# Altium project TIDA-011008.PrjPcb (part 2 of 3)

## Sheet TIDA-011008_Control Stage.SchDoc
size 558 x 431 mm; Date: Not shown in title block; ApprovedBy: Not shown in title block; CheckedBy: Not shown in title block; Author: Not shown in title block; CompanyName: Not shown in title block; Engineer: Not shown in title block; Organization: Not shown in title block; Address1: Not shown in title block; Address2: Not shown in title block; Address3: Not shown in title block; Address4: Not shown in title block; DocumentNumber: 1; Revision: Use project parameter SCH_Rev; SheetNumber: 9; SheetTotal: 10; PageSetup: Record=PageOptions¦CenterHorizontal=True¦CenterVertical=True¦PrintScale=1.00¦XCorrection=1.00¦YCorrection=1.00¦PrintKind=0¦BorderSize=5000000¦LeftOffset=0¦BottomOffset=0¦Orientation=2¦PaperLength=1000¦PaperWidth=1000¦Scale=100¦PaperSource=15¦PrintQuality=600¦MediaType=1¦DitherType=10¦PaperKind=Letter¦PrintScaleMode=1
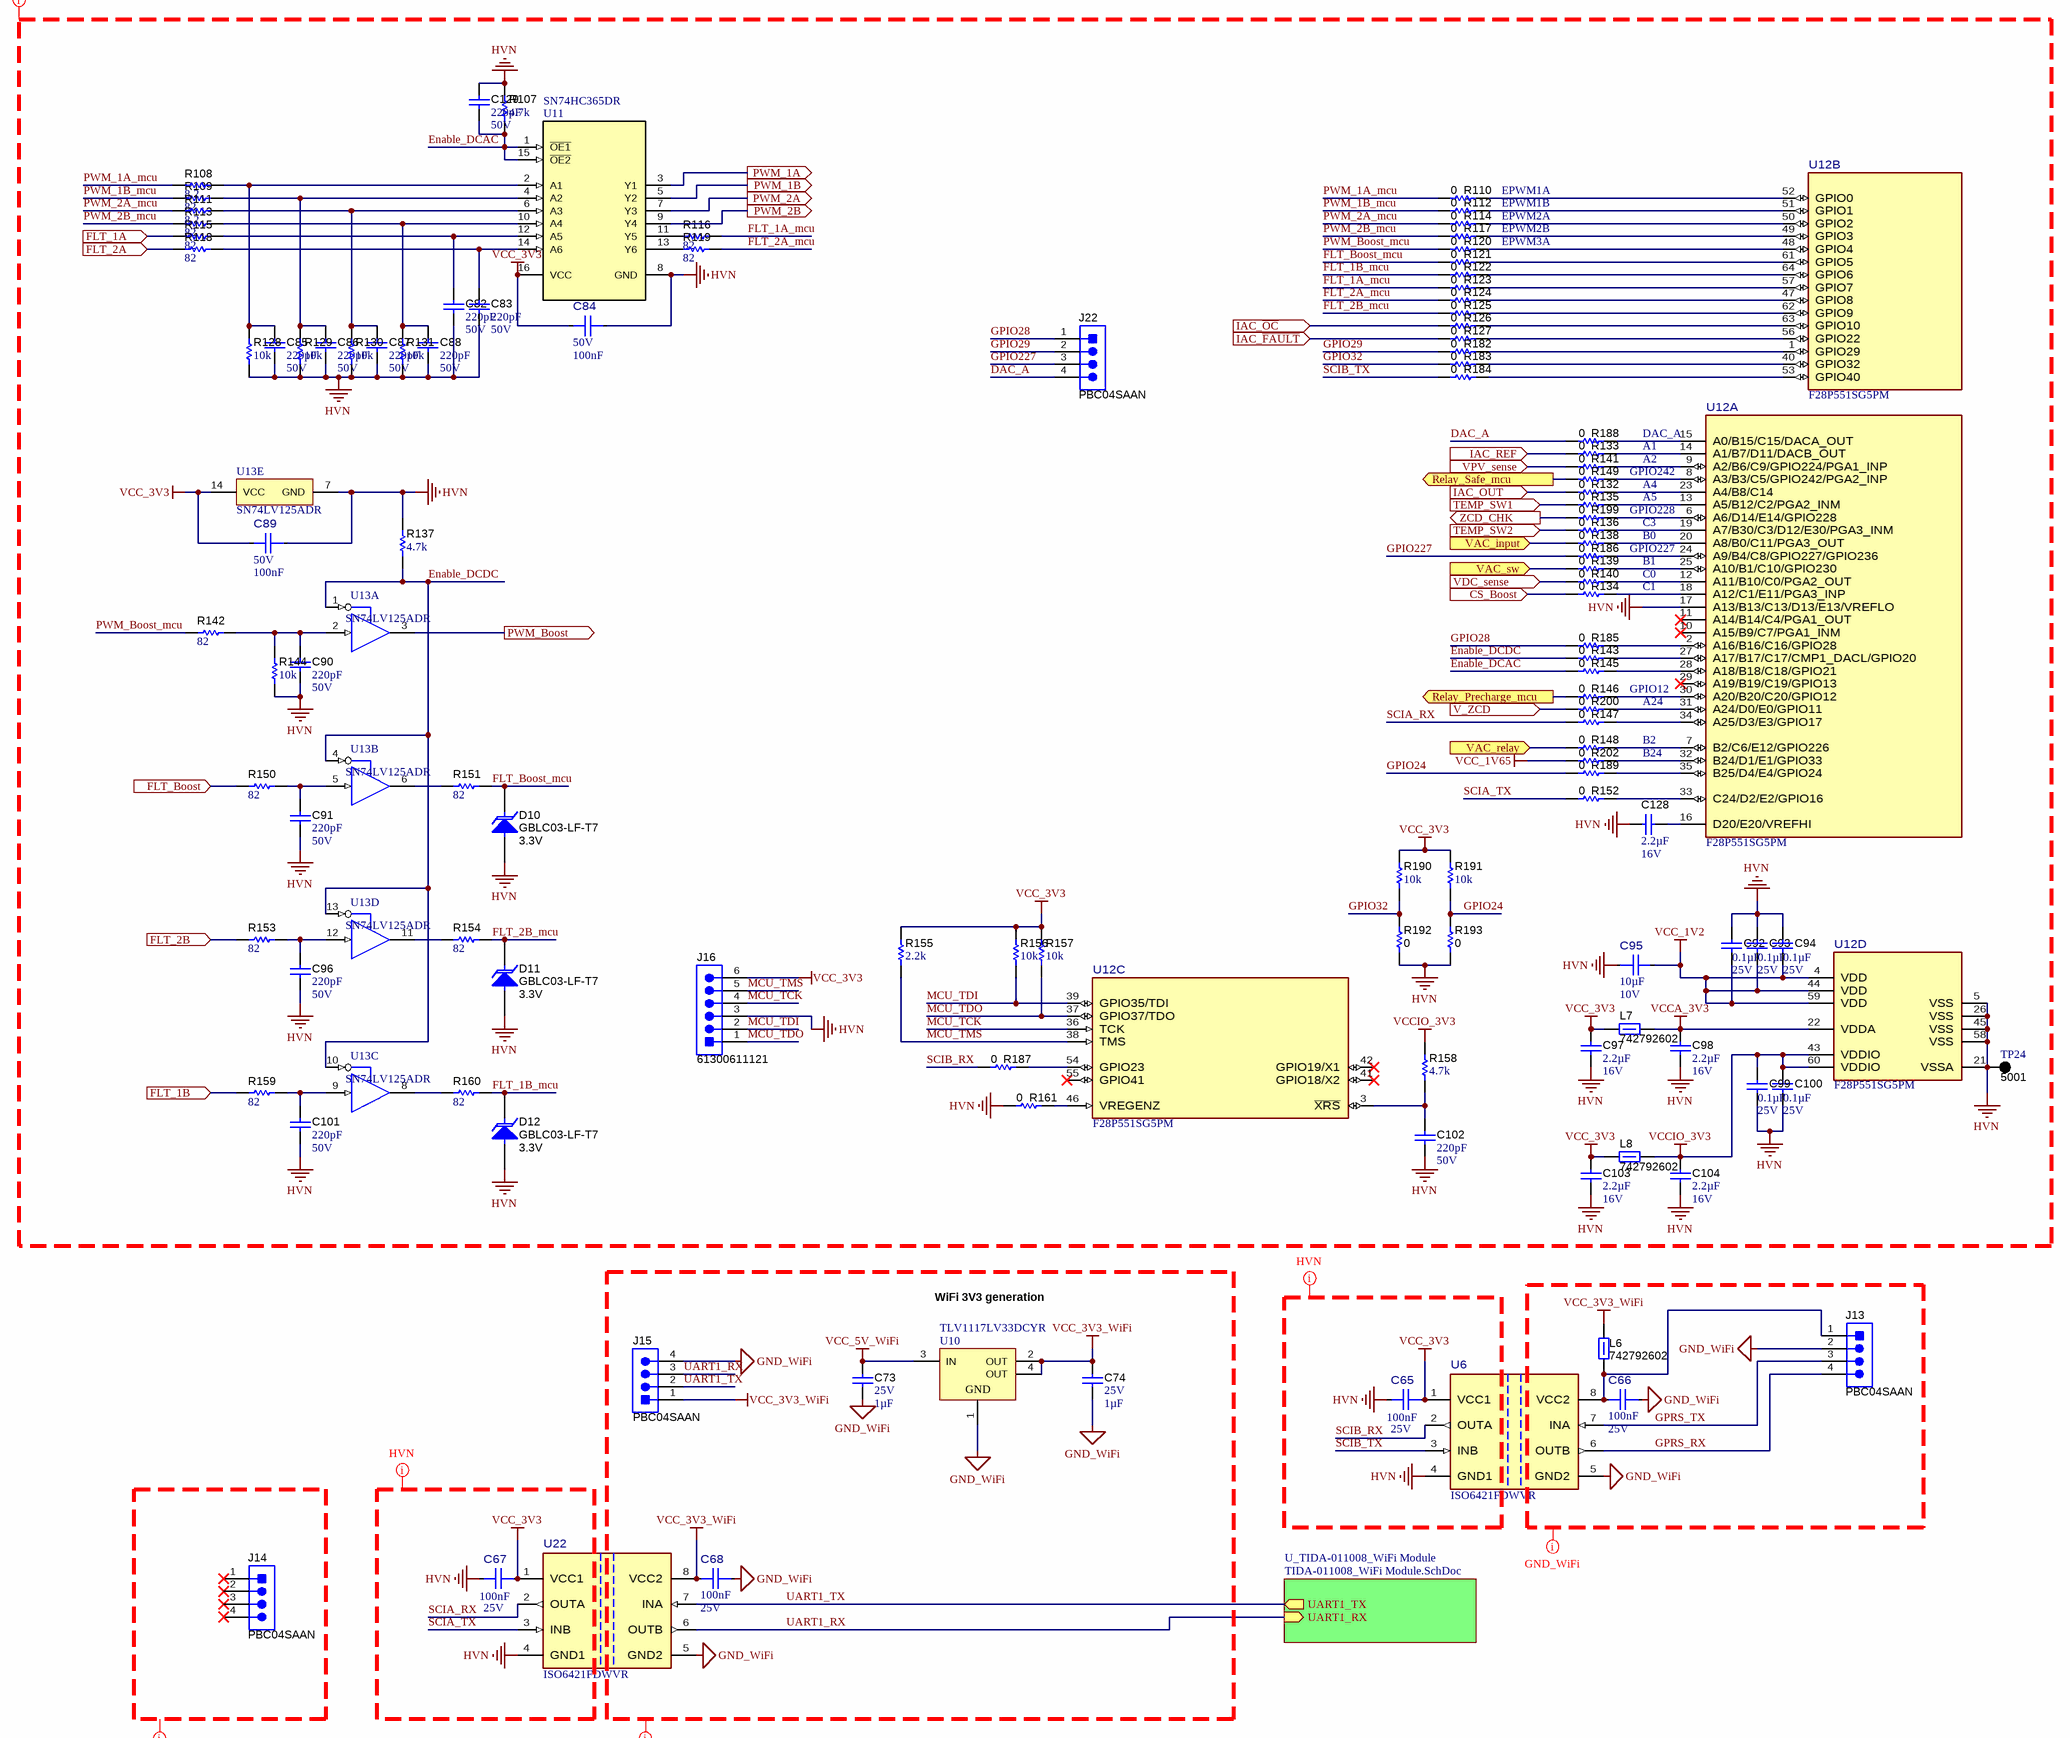
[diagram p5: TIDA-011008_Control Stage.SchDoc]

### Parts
C65  ValueDisplayed: 100nF  VDC_V: 25V  [FP-C1608X8R1E104K080AA_0603-MFG]  (hidden comment: C1608X8R1E104K080AA)
C66  ValueDisplayed: 100nF  VDC_V: 25V  [FP-C1608X8R1E104K080AA_0603-MFG]  (hidden comment: C1608X8R1E104K080AA)
C67  ValueDisplayed: 100nF  VDC_V: 25V  [FP-C1608X8R1E104K080AA_0603-MFG]  (hidden comment: C1608X8R1E104K080AA)
C68  ValueDisplayed: 100nF  VDC_V: 25V  [FP-C1608X8R1E104K080AA_0603-MFG]  (hidden comment: C1608X8R1E104K080AA)
C73  VDC_V: 25V  ValueDisplayed: 1µF  [0603]  (hidden comment: TMK107BJ105KA-T)
C74  VDC_V: 25V  ValueDisplayed: 1µF  [0603]  (hidden comment: TMK107BJ105KA-T)
C82  Cap_F: 220pF  VDC_V: 50V  [0603]  (hidden comment: C0603C221K5RACTU)
C83  Cap_F: 220pF  VDC_V: 50V  [0603]  (hidden comment: C0603C221K5RACTU)
C84  VDC_V: 50V  Cap_F: 100nF  [FP-GCM188R71H104KA57J_0603-MFG]  (hidden comment: GCM188R71H104KA57J)
C85  Cap_F: 220pF  VDC_V: 50V  [0603]  (hidden comment: C0603C221K5RACTU)
C86  Cap_F: 220pF  VDC_V: 50V  [0603]  (hidden comment: C0603C221K5RACTU)
C87  Cap_F: 220pF  VDC_V: 50V  [0603]  (hidden comment: C0603C221K5RACTU)
C88  Cap_F: 220pF  VDC_V: 50V  [0603]  (hidden comment: C0603C221K5RACTU)
C89  VDC_V: 50V  Cap_F: 100nF  [FP-GCM188R71H104KA57J_0603-MFG]  (hidden comment: GCM188R71H104KA57J)
C90  Cap_F: 220pF  VDC_V: 50V  [0603]  (hidden comment: C0603C221K5RACTU)
C91  Cap_F: 220pF  VDC_V: 50V  [0603]  (hidden comment: C0603C221K5RACTU)
C92  ValueDisplayed: 0.1µF  VDC_V: 25V  [0402]  (hidden comment: GCM155L81E104KE02D)
C93  ValueDisplayed: 0.1µF  VDC_V: 25V  [0402]  (hidden comment: GCM155L81E104KE02D)
C94  ValueDisplayed: 0.1µF  VDC_V: 25V  [0402]  (hidden comment: GCM155L81E104KE02D)
C95  Cap_F: 10µF  VDC_V: 10V  [FP-GRM188Z71A106KA73D_0603-MFG]  (hidden comment: GRM188Z71A106KA73D)
C96  Cap_F: 220pF  VDC_V: 50V  [0603]  (hidden comment: C0603C221K5RACTU)
C97  Cap_F: 2.2µF  VDC_V: 16V  [0603]  (hidden comment: CC0603KRX7R7BB225)
C98  Cap_F: 2.2µF  VDC_V: 16V  [0603]  (hidden comment: CC0603KRX7R7BB225)
C99  ValueDisplayed: 0.1µF  VDC_V: 25V  [0402]  (hidden comment: GCM155L81E104KE02D)
C100  ValueDisplayed: 0.1µF  VDC_V: 25V  [0402]  (hidden comment: GCM155L81E104KE02D)
C101  Cap_F: 220pF  VDC_V: 50V  [0603]  (hidden comment: C0603C221K5RACTU)
C102  Cap_F: 220pF  VDC_V: 50V  [0603]  (hidden comment: C0603C221K5RACTU)
C103  Cap_F: 2.2µF  VDC_V: 16V  [0603]  (hidden comment: CC0603KRX7R7BB225)
C104  Cap_F: 2.2µF  VDC_V: 16V  [0603]  (hidden comment: CC0603KRX7R7BB225)
C128  Cap_F: 2.2µF  VDC_V: 16V  [0603]  (hidden comment: CC0603KRX7R7BB225)
C129  Cap_F: 220pF  VDC_V: 50V  [0603]  (hidden comment: C0603C221K5RACTU)
D10  GBLC03-LF-T7  value 3.3V  [SOD-323]
D11  GBLC03-LF-T7  value 3.3V  [SOD-323]
D12  GBLC03-LF-T7  value 3.3V  [SOD-323]
J13  PBC04SAAN  [Sullins_xxC04SAAN]
J14  PBC04SAAN  [Sullins_xxC04SAAN]
J15  PBC04SAAN  [Sullins_xxC04SAAN]
J16  61300611121  [WURTH_61300611121]
J22  PBC04SAAN  [Sullins_xxC04SAAN]
L6  742792602  [0603]
L7  742792602  [0603]
L8  742792602  [0603]
R107  ValueDisplayed: 4.7k  [0603]  (hidden comment: CR0603-JW-472GLF)
R108  ValueDisplayed: 8.2  [0603]  (hidden comment: CRCW06038R20JNEA)
R109  ValueDisplayed: 82  [0603]  (hidden comment: CRCW060382R0JNEA)
R110  ValueDisplayed: 0  [0603]  (hidden comment: RCS06030000Z0EA)
R111  ValueDisplayed: 8.2  [0603]  (hidden comment: CRCW06038R20JNEA)
R112  ValueDisplayed: 0  [0603]  (hidden comment: RCS06030000Z0EA)
R113  ValueDisplayed: 82  [0603]  (hidden comment: CRCW060382R0JNEA)
R114  ValueDisplayed: 0  [0603]  (hidden comment: RCS06030000Z0EA)
R115  ValueDisplayed: 82  [0603]  (hidden comment: CRCW060382R0JNEA)
R116  ValueDisplayed: 82  [0603]  (hidden comment: CRCW060382R0JNEA)
R117  ValueDisplayed: 0  [0603]  (hidden comment: RCS06030000Z0EA)
R118  ValueDisplayed: 82  [0603]  (hidden comment: CRCW060382R0JNEA)
R119  ValueDisplayed: 82  [0603]  (hidden comment: CRCW060382R0JNEA)
R120  ValueDisplayed: 0  [0603]  (hidden comment: RCS06030000Z0EA)
R121  ValueDisplayed: 0  [0603]  (hidden comment: RCS06030000Z0EA)
R122  ValueDisplayed: 0  [0603]  (hidden comment: RCS06030000Z0EA)
R123  ValueDisplayed: 0  [0603]  (hidden comment: RCS06030000Z0EA)
R124  ValueDisplayed: 0  [0603]  (hidden comment: RCS06030000Z0EA)
R125  ValueDisplayed: 0  [0603]  (hidden comment: RCS06030000Z0EA)
R126  ValueDisplayed: 0  [0603]  (hidden comment: RCS06030000Z0EA)
R127  ValueDisplayed: 0  [0603]  (hidden comment: RCS06030000Z0EA)
R128  ValueDisplayed: 10k  [0603]  (hidden comment: RC1608J103CS)
R129  ValueDisplayed: 10k  [0603]  (hidden comment: RC1608J103CS)
R130  ValueDisplayed: 10k  [0603]  (hidden comment: RC1608J103CS)
R131  ValueDisplayed: 10k  [0603]  (hidden comment: RC1608J103CS)
R132  ValueDisplayed: 0  [0603]  (hidden comment: RCS06030000Z0EA)
R133  ValueDisplayed: 0  [0603]  (hidden comment: RCS06030000Z0EA)
R134  ValueDisplayed: 0  [0603]  (hidden comment: RCS06030000Z0EA)
R135  ValueDisplayed: 0  [0603]  (hidden comment: RCS06030000Z0EA)
R136  ValueDisplayed: 0  [0603]  (hidden comment: RCS06030000Z0EA)
R137  ValueDisplayed: 4.7k  [0603]  (hidden comment: CR0603-JW-472GLF)
R138  ValueDisplayed: 0  [0603]  (hidden comment: RCS06030000Z0EA)
R139  ValueDisplayed: 0  [0603]  (hidden comment: RCS06030000Z0EA)
R140  ValueDisplayed: 0  [0603]  (hidden comment: RCS06030000Z0EA)
R141  ValueDisplayed: 0  [0603]  (hidden comment: RCS06030000Z0EA)
R142  ValueDisplayed: 82  [0603]  (hidden comment: CRCW060382R0JNEA)
R143  ValueDisplayed: 0  [0603]  (hidden comment: RCS06030000Z0EA)
R144  ValueDisplayed: 10k  [0603]  (hidden comment: RC1608J103CS)
R145  ValueDisplayed: 0  [0603]  (hidden comment: RCS06030000Z0EA)
R146  ValueDisplayed: 0  [0603]  (hidden comment: RCS06030000Z0EA)
R147  ValueDisplayed: 0  [0603]  (hidden comment: RCS06030000Z0EA)
R148  ValueDisplayed: 0  [0603]  (hidden comment: RCS06030000Z0EA)
R149  ValueDisplayed: 0  [0603]  (hidden comment: RCS06030000Z0EA)
R150  ValueDisplayed: 82  [0603]  (hidden comment: CRCW060382R0JNEA)
R151  ValueDisplayed: 82  [0603]  (hidden comment: CRCW060382R0JNEA)
R152  ValueDisplayed: 0  [0603]  (hidden comment: RCS06030000Z0EA)
R153  ValueDisplayed: 82  [0603]  (hidden comment: CRCW060382R0JNEA)
R154  ValueDisplayed: 82  [0603]  (hidden comment: CRCW060382R0JNEA)
R155  ValueDisplayed: 2.2k  [0603]  (hidden comment: RC0603JR-072K2L)
R156  ValueDisplayed: 10k  [0603]  (hidden comment: RC1608J103CS)
R157  ValueDisplayed: 10k  [0603]  (hidden comment: RC1608J103CS)
R158  ValueDisplayed: 4.7k  [0603]  (hidden comment: CR0603-JW-472GLF)
R159  ValueDisplayed: 82  [0603]  (hidden comment: CRCW060382R0JNEA)
R160  ValueDisplayed: 82  [0603]  (hidden comment: CRCW060382R0JNEA)
R161  ValueDisplayed: 0  [0603]  (hidden comment: RCS06030000Z0EA)
R182  ValueDisplayed: 0  [0603]  (hidden comment: RCS06030000Z0EA)
R183  ValueDisplayed: 0  [0603]  (hidden comment: RCS06030000Z0EA)
R184  ValueDisplayed: 0  [0603]  (hidden comment: RCS06030000Z0EA)
R185  ValueDisplayed: 0  [0603]  (hidden comment: RCS06030000Z0EA)
R186  ValueDisplayed: 0  [0603]  (hidden comment: RCS06030000Z0EA)
R187  ValueDisplayed: 0  [0603]  (hidden comment: RCS06030000Z0EA)
R188  ValueDisplayed: 0  [0603]  (hidden comment: RCS06030000Z0EA)
R189  ValueDisplayed: 0  [0603]  (hidden comment: RCS06030000Z0EA)
R190  ValueDisplayed: 10k  [0603]  (hidden comment: RC1608J103CS)
R191  ValueDisplayed: 10k  [0603]  (hidden comment: RC1608J103CS)
R192  ValueDisplayed: 0  [0603]  (hidden comment: RCS06030000Z0EA)
R193  ValueDisplayed: 0  [0603]  (hidden comment: RCS06030000Z0EA)
R199  ValueDisplayed: 0  [0603]  (hidden comment: RCS06030000Z0EA)
R200  ValueDisplayed: 0  [0603]  (hidden comment: RCS06030000Z0EA)
R202  ValueDisplayed: 0  [0603]  (hidden comment: RCS06030000Z0EA)
TP24  5001  [Keystone5001]
U6  ISO6421FDWVR  [DWV0008A-MFG]
U10  TLV1117LV33DCYR  [DCY0004A_N]
U11  SN74HC365DR  [D0016A_L]
U12  F28P551SG5PM  [PM0064A-MFG]  (parts A,B,C,D of 4)
U13  SN74LV125ADR  [D0014A_L]  (parts A,B,C,D,E of 5)
U22  ISO6421FDWVR  [DWV0008A-MFG]

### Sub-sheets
U_TIDA-011008_WiFi Module = TIDA-011008_WiFi Module.SchDoc: UART1_TX (out), UART1_RX (in)

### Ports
CS_Boost (in), FLT_1A (in), FLT_1B (in), FLT_2A (in), FLT_2B (in), FLT_Boost (in), IAC_OUT (in), IAC_REF (in), IAC_~{FAULT} (in), IAC_~{OC} (in), PWM_1A (out), PWM_1B (out), PWM_2A (out), PWM_2B (out), PWM_Boost (out), Relay_Precharge_mcu (out), Relay_Safe_mcu (out), TEMP_SW1 (in), TEMP_SW2 (in), V_ZCD (in), VAC_input (in), VAC_relay (in), VAC_sw (in), VDC_sense (in), VPV_sense (in), ZCD_CHK (out)

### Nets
GND_WiFi: C66.1 C68.1 C73.1 C74.1 J13.2 J15.4 U6.5(GND2) U10.1(GND) U22.5(GND2)
HVN: C65.2 C67.2 C82.2 C83.2 C84.1 C85.2 C86.2 C87.2 C88.2 C89.1 C90.2 C91.2 C92.1 C93.1 C94.1 C95.1 C96.2 C97.2 C98.2 C99.2 C100.2 C101.2 C102.2 C103.2 C104.2 C128.1 C129.1 D10.2(A) D11.2(A) D12.2(A) J16.3 R107.2 R128.1 R129.1 R130.1 R131.1 R137.2 R144.1 R161.2 R192.2 R193.2 TP24.1 U6.4(GND1) U11.8(GND) U12.5(VSS) U12.17(A13/B13/C13/D13/E13/VREFLO) U12.21(VSSA) U12.26(VSS) U12.45(VSS) U12.58(VSS) U13.7(GND) U22.4(GND1)  [project net DC_Bus-]
VCC_1V2: C92.2 C93.2 C94.2 C95.2 U12.4(VDD) U12.44(VDD) U12.59(VDD)
VCC_1V65: R202.2
VCC_3V3: C65.1 C67.1 C84.2 C89.2 C97.1 C103.1 J16.6 L7.1 L8.1 R155.2 R156.2 R157.2 R190.2 R191.2 U6.1(VCC1) U11.16(VCC) U13.14(VCC) U22.1(VCC1)
VCC_3V3_WiFi: C68.2 C74.2 J15.1 L6.1 U10.2(OUT) U10.4(OUT) U22.8(VCC2)
VCC_5V_WiFi: C73.2 U10.3(IN)
VCCA_3V3: C98.1 L7.2 U12.22(VDDA)
VCCIO_3V3: C99.1 C100.1 C104.1 L8.2 R158.2 U12.43(VDDIO) U12.60(VDDIO)
CS_Boost: R134.2 ; port CS_Boost
DAC_A: J22.4 R188.2
Enable_DCAC: C129.2 R107.1 R145.2 U11.1(~{OE1}) U11.15(~{OE2})
Enable_DCDC: R137.1 R143.2 U13.1(1~{OE}) U13.4(2~{OE}) U13.10(3~{OE}) U13.13(4~{OE})
FLT_1A: R115.1 ; port FLT_1A
FLT_1A_mcu: R116.2 R123.2
FLT_1B: R159.1 ; port FLT_1B
FLT_1B_mcu: D12.1(K) R122.2 R160.2
FLT_2A: R118.1 ; port FLT_2A
FLT_2A_mcu: R119.2 R124.2
FLT_2B: R153.1 ; port FLT_2B
FLT_2B_mcu: D11.1(K) R125.2 R154.2
FLT_Boost: R150.1 ; port FLT_Boost
FLT_Boost_mcu: D10.1(K) R121.2 R151.2
GPIO24: R189.2 R191.1 R193.1
GPIO28: J22.1 R185.2
GPIO29: J22.2 R182.2
GPIO32: R183.2 R190.1 R192.1
GPIO227: J22.3 R186.2
GPRS_RX: J13.4 U6.6(OUTB)
GPRS_TX: J13.3 U6.7(INA)
IAC_~{FAULT}: R127.2 ; port IAC_~{FAULT}
IAC_~{OC}: R126.2 ; port IAC_~{OC}
IAC_OUT: R132.2 ; port IAC_OUT
IAC_REF: R133.2 ; port IAC_REF
MCU_TCK: J16.4 U12.36(TCK)
MCU_TDI: J16.2 R156.1 U12.39(GPIO35/TDI)
MCU_TDO: J16.1 R157.1 U12.37(GPIO37/TDO)
MCU_TMS: J16.5 R155.1 U12.38(TMS)
PWM_1A: U11.3(Y1) ; port PWM_1A
PWM_1A_mcu: R108.1 R110.2
PWM_1B: U11.5(Y2) ; port PWM_1B
PWM_1B_mcu: R109.1 R112.2
PWM_2A: U11.7(Y3) ; port PWM_2A
PWM_2A_mcu: R111.1 R114.2
PWM_2B: U11.9(Y4) ; port PWM_2B
PWM_2B_mcu: R113.1 R117.2
PWM_Boost: U13.3(1Y) ; port PWM_Boost
PWM_Boost_mcu: R120.2 R142.1
Relay_Precharge_mcu: R146.2 ; port Relay_Precharge_mcu
Relay_Safe_mcu: R149.2 ; port Relay_Safe_mcu
SCIA_RX: R147.2 U22.2(OUTA)
SCIA_TX: R152.2 U22.3(INB)
SCIB_RX: R187.2 U6.2(OUTA)
SCIB_TX: R184.2 U6.3(INB)
TEMP_SW1: R135.2 ; port TEMP_SW1
TEMP_SW2: R136.2 ; port TEMP_SW2
UART1_RX: J15.3 U22.6(OUTB) ; sheet U_TIDA-011008_WiFi Module/UART1_RX
UART1_TX: J15.2 U22.7(INA) ; sheet U_TIDA-011008_WiFi Module/UART1_TX
V_ZCD: R200.2 ; port V_ZCD
VAC_input: R138.2 ; port VAC_input
VAC_relay: R148.2 ; port VAC_relay
VAC_sw: R139.2 ; port VAC_sw
VDC_sense: R140.2 ; port VDC_sense
VPV_sense: R141.2 ; port VPV_sense
ZCD_CHK: R199.2 ; port ZCD_CHK
NetC66_2: C66.2 J13.1 L6.2 U6.8(VCC2)
NetC82_1: C82.1 R115.2 U11.12(A5)
NetC83_1: C83.1 R118.2 U11.14(A6)
NetC85_1: C85.1 R108.2 R128.2 U11.2(A1)
NetC86_1: C86.1 R109.2 R129.2 U11.4(A2)
NetC87_1: C87.1 R111.2 R130.2 U11.6(A3)
NetC88_1: C88.1 R113.2 R131.2 U11.10(A4)
NetC90_1: C90.1 R142.2 R144.2 U13.2(1A)
NetC91_1: C91.1 R150.2 U13.5(2A)
NetC96_1: C96.1 R153.2 U13.12(4A)
NetC101_1: C101.1 R159.2 U13.9(3A)
NetC102_1: C102.1 R158.1 U12.3(~{XRS})
NetC128_2: C128.2 U12.16(D20/E20/VREFHI)
NetR110_1: R110.1 U12.52(GPIO0)
NetR112_1: R112.1 U12.51(GPIO1)
NetR114_1: R114.1 U12.50(GPIO2)
NetR116_1: R116.1 U11.11(Y5)
NetR117_1: R117.1 U12.49(GPIO3)
NetR119_1: R119.1 U11.13(Y6)
NetR120_1: R120.1 U12.48(GPIO4)
NetR121_1: R121.1 U12.61(GPIO5)
NetR122_1: R122.1 U12.64(GPIO6)
NetR123_1: R123.1 U12.57(GPIO7)
NetR124_1: R124.1 U12.47(GPIO8)
NetR125_1: R125.1 U12.62(GPIO9)
NetR126_1: R126.1 U12.63(GPIO10)
NetR127_1: R127.1 U12.56(GPIO22)
NetR132_1: R132.1 U12.23(A4/B8/C14)
NetR133_1: R133.1 U12.14(A1/B7/D11/DACB_OUT)
NetR134_1: R134.1 U12.18(A12/C1/E11/PGA3_INP)
NetR135_1: R135.1 U12.13(A5/B12/C2/PGA2_INM)
NetR136_1: R136.1 U12.19(A7/B30/C3/D12/E30/PGA3_INM)
NetR138_1: R138.1 U12.20(A8/B0/C11/PGA3_OUT)
NetR139_1: R139.1 U12.25(A10/B1/C10/GPIO230)
NetR140_1: R140.1 U12.12(A11/B10/C0/PGA2_OUT)
NetR141_1: R141.1 U12.9(A2/B6/C9/GPIO224/PGA1_INP)
NetR143_1: R143.1 U12.27(A17/B17/C17/CMP1_DACL/GPIO20)
NetR145_1: R145.1 U12.28(A18/B18/C18/GPIO21)
NetR146_1: R146.1 U12.30(A20/B20/C20/GPIO12)
NetR147_1: R147.1 U12.34(A25/D3/E3/GPIO17)
NetR148_1: R148.1 U12.7(B2/C6/E12/GPIO226)
NetR149_1: R149.1 U12.8(A3/B3/C5/GPIO242/PGA2_INP)
NetR151_1: R151.1 U13.6(2Y)
NetR152_1: R152.1 U12.33(C24/D2/E2/GPIO16)
NetR154_1: R154.1 U13.11(4Y)
NetR160_1: R160.1 U13.8(3Y)
NetR161_1: R161.1 U12.46(VREGENZ)
NetR182_1: R182.1 U12.1(GPIO29)
NetR183_1: R183.1 U12.40(GPIO32)
NetR184_1: R184.1 U12.53(GPIO40)
NetR185_1: R185.1 U12.2(A16/B16/C16/GPIO28)
NetR186_1: R186.1 U12.24(A9/B4/C8/GPIO227/GPIO236)
NetR187_1: R187.1 U12.54(GPIO23)
NetR188_1: R188.1 U12.15(A0/B15/C15/DACA_OUT)
NetR189_1: R189.1 U12.35(B25/D4/E4/GPIO24)
NetR199_1: R199.1 U12.6(A6/D14/E14/GPIO228)
NetR200_1: R200.1 U12.31(A24/D0/E0/GPIO11)
NetR202_1: R202.1 U12.32(B24/D1/E1/GPIO33)

Not connected (* = marked no-connect by the designer): J14 1* 2* 3* 4*; U12 10(A15/B9/C7/PGA1_INM)* 11(A14/B14/C4/PGA1_OUT)* 29(A19/B19/C19/GPIO13)* 41(GPIO18/X2)* 42(GPIO19/X1)* 55(GPIO41)*

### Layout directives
net class HVN: DAC_A, Enable_DCAC, Enable_DCDC, FLT_1A_mcu, FLT_1B_mcu, FLT_2A_mcu, FLT_2B_mcu, FLT_Boost_mcu, GPIO24, GPIO28, GPIO29, GPIO32, GPIO227, HVN, MCU_TCK, MCU_TDI, MCU_TDO, MCU_TMS, PWM_1A_mcu, PWM_1B_mcu, PWM_2A_mcu, PWM_2B_mcu, PWM_Boost_mcu, SCIA_RX, SCIA_TX, SCIB_RX, SCIB_TX, VCC_1V2, VCC_1V65, VCC_3V3, VCCA_3V3, VCCIO_3V3
net class GND_WiFi: (no net found under the mark), GND_WiFi, GPRS_RX, GPRS_TX, UART1_RX, UART1_TX, VCC_3V3_WiFi, VCC_5V_WiFi

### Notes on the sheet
- EPWM1A
- EPWM1B
- EPWM2A
- EPWM2B
- EPWM3A
- GPIO242
- A4
- A1
- A2
- DAC_A
- GPIO228
- GPIO227
- A5
- C3
- B0
- C1
- B1
- C0
- GPIO12
- B2
- A24
- B24
- WiFi 3V3 generation

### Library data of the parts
C65-C68 = CMP-0089959-1: 0.1µF ±10% 25V Ceramic Capacitor X8R 0603 (1608 Metric); Manufacturer: TDK Corporation; SizeZ_mm: 0.9mm; TempCo: 15%; AEC Qualified: No; Value: 100nF
C73 C74 = CMP-0086152-1: CAP, CERM, 1 µF, 25 V,+/- 10%, X5R, 0603; Manufacturer: Taiyo Yuden; SizeAreaWB_mm2: 4.68; SizeZ_mm: 1; U/M: EA; Green_REACh: Passed; Value: 1uF; AEC Qualified: N; TaMax_C: 85°C; Green_Lifecycle: Active; AEC Category: Q200; SizeArea_mm2: 1.28; TaMin_C: -55°C; SizeY_mm: 0.8; SizeX_mm: 1.6
C82 C83 C85-C88 C90 C91 C96 C101 C102 C129 = CMP-0006895-4: CAP, CERM, 220 pF, 50 V, +/- 10%, X7R, 0603; Manufacturer: Kemet; TaMin_C: -55°C; Polarized: N; SizeAreaWB_mm2: 4.68; Value1: Unknown; U/M: EA; Value: 220pF; TaMax_C: 125°C; SizeZ_mm: 1; SizeX_mm: 1.6; SizeY_mm: 0.8; SizeArea_mm2: 1.28; AEC Category: Q200
C84 C89 = CMP-0095617-1: 0603 50 V 0.1 uF X7R ±10% Tolerance SMT Multilayer Ceramic Capacitor; Manufacturer: Murata; TempCo: 15%; SizeZ_mm: 0.9mm; AEC Qualified: No; ValueDisplayed: 0.1uF; Value: 100nF
C92-C94 C99 C100 = CMP-0861000-1: CAP, CERM, 0.1 µF, 25 V,+/- 10%, X8L, AEC-Q200 Grade 0, 0402; Manufacturer: MuRata; U/M: EA; Polarized: N; Cap_F: 100nF; SizeZ_mm: 0.6; SizeY_mm: 0.5; Value: 0.1uF; SizeX_mm: 1; AEC Qualified: Y; AEC Grade: 0; SizeAreaWB_mm2: 3; AEC Category: Q200; TaMin_C: -55°C; TaMax_C: 150°C
C95 = CMP-0125957-1: Chip Multilayer Ceramic Capacitors for General Purpose, 0603, 10uF, X7R, 15%, 10%, 10V; Manufacturer: Murata; AEC Qualified: No; SizeZ_mm: 1mm; Value: 10µF
C97 C98 C103 C104 C128 = CMP-0079605-1: CAP, CERM, 2.2 µF, 16 V,+/- 10%, X7R, 0603; Manufacturer: Yageo America; TaMin_C: -55°C; Polarized: N; SizeAreaWB_mm2: 4.68; U/M: EA; Value: 2.2uF; TaMax_C: 125°C; SizeZ_mm: 1; SizeX_mm: 1.6; SizeY_mm: 0.8; SizeArea_mm2: 1.28; AEC Category: Q200
D10-D12 = CMP-0005826-3: Diode, TVS, Uni, 3.3 V, SOD-323; Manufacturer: Protek Devices; Value1: 350W; SizeY_mm: 1.35; SizeArea_mm2: 3.645; SizeAreaWB_mm2: 8.695; SizeZ_mm: 1; AEC Category: Q101; Vbr_Min: 4V; SizeX_mm: 2.7
J13-J15 J22 = CMP-0054583-1: Header, 2.54 mm, 4x1, Gold, TH; Manufacturer: Sullins Connector Solutions; CNHeader: TRUE; Current_A: 3A; Green_Lifecycle: Not Set; Shrouded: N; Gender: Male; Green_REACh: Incomplete; Voltage_V: 1.8kV; Row_Count: 1; Pitch_mm: 2.54; CT: FALSE; Cert_UL: Y
J16 = CMP-0054801-2: Header, 2.54 mm, 6x1, Gold, TH; Manufacturer: Wurth Elektronik; Cert_UL: Y; Gender: Male; Row_Count: 1; Shrouded: N; Pitch_mm: 2.54
L6-L8 = CMP-0003173-2: Ferrite Bead, 60 ohm @ 100 MHz, 3 A, 0603; Manufacturer: Wurth Elektronik; Ztyp@1GHz_Ohm: 110.436; ZTyp@100MHz_Ohm: 60; SizeAreaWB_mm2: 4.68; DCR_ohm: 0.04; Value1: 0.04 ohm; Value: 60 ohm; Imax_A: 3A; SizeZ_mm: 1; SizeX_mm: 1.6; SizeY_mm: 0.8; SizeArea_mm2: 1.28
R107 R137 R158 = CMP-0025696-3: RES, 4.7 k, 5%, 0.1 W, 0603; Manufacturer: Bourns; Power_W: 100mW; TempCo: 200 ppm/C; Value_Code: 4k70; U/M: EA; Value: 4.7k; EIA_Code: E24; SizeX_mm: 1.6; SizeY_mm: 0.8; SizeZ_mm: 1; Value2: 0.1W; SizeArea_mm2: 1.28; AEC Qualified: N; VDC_V: 50V; AEC Category: Q200
R108 R111 = CMP-0025864-4: RES, 8.2, 5%, 0.1 W, AEC-Q200 Grade 0, 0603; Manufacturer: Vishay-Dale; Power_W: 100mW; TempCo: 200 ppm/C; Value_Code: 8R20; Value: 8.2; EIA_Code: E24; SizeX_mm: 1.6; SizeY_mm: 0.8; SizeZ_mm: 1; Value2: 0.1W; SizeArea_mm2: 1.28; AEC Qualified: Y; VDC_V: 75V; AEC Category: Q200; AEC Grade: 0
R109 R113 R115 R116 R118 R119 R142 R150 R151 R153 R154 R159 R160 = CMP-0025861-4: RES, 82, 5%, 0.1 W, AEC-Q200 Grade 0, 0603; Manufacturer: Vishay-Dale; Power_W: 100mW; TempCo: 200 ppm/C; Value_Code: 82R0; Value: 82; EIA_Code: E24; SizeX_mm: 1.6; SizeY_mm: 0.8; SizeZ_mm: 1; Value2: 0.1W; SizeArea_mm2: 1.28; AEC Qualified: Y; VDC_V: 75V; AEC Category: Q200; AEC Grade: 0
R110 R112 R114 R117 R120-R127 R132-R136 R138-R141 R143 R145-R149 R152 R161 R182-R189 R192 R193 R199 R200 R202 = CMP-0081973-1: RES, 0, 0%, 0.25 W, AEC-Q200 Grade 0, 0603; Manufacturer: Vishay-Dale; SizeAreaWB_mm2: 4.68; SizeArea_mm2: 1.28; AEC Qualified: Y; AEC Category: Q200; Value: 0; SizeZ_mm: 1; SizeY_mm: 0.8; Power_W: 250mW; Value2: 0.25W; SizeX_mm: 1.6
R128-R131 R144 R156 R157 R190 R191 = CMP-0025945-3: RES, 10 k, 5%, 0.1 W, 0603; Manufacturer: Samsung Electro-Mechanics; Power_W: 100mW; TempCo: 100 ppm/C; Value_Code: 10k0; U/M: EA; Value: 10k; EIA_Code: E24; SizeX_mm: 1.6; SizeY_mm: 0.8; SizeZ_mm: 1; Value2: 0.1W; SizeArea_mm2: 1.28; AEC Qualified: N; VDC_V: 31V; AEC Category: Q200
R155 = CMP-0025906-5: RES, 2.2 k, 5%, 0.1 W, 0603; Manufacturer: Yageo; Power_W: 100mW; TempCo: 100 ppm/C; Value_Code: 2k20; Value: 2.2k; EIA_Code: E24; SizeX_mm: 1.6; SizeY_mm: 0.8; SizeZ_mm: 1; Value2: 0.1W; SizeArea_mm2: 1.28; VDC_V: 75V; SizeAreaWB_mm2: 4.68; AEC Qualified: N; AEC Category: Q200
TP24 = CMP-0055138-2: Test Point, Miniature, Black, TH; Manufacturer: Keystone Electronics; ContactFinish: Silver; CNHeader: FALSE; Green_Lifecycle: Active; Green_REACh: Passed; CT: TRUE
U6 U22 = CMP-0127286-1: Manufacturer: Texas Instruments; SizeZ_mm: 2.8mm; Standoff Height: 0.36mm
U10 = CMP-0036760-1: Single Output LDO, 1 A, Fixed 3.3 V Output, 2 to 5.5 V Input, 4-pin SOT-223 (DCY), -40 to 125 degC, Green (RoHS & no Sb/Br); Manufacturer: Texas Instruments; Accuracy(%): 2; Vdo(Typ)(mV): 1200; SubFamily: Single Channel LDO; Vout Adj(Min)(V): 3.3; Vin(Max)(V): 5.5; Iout(Max)(A): 1; Iq(Typ)(mA): 0.05
U11 = CMP-0047248-1: Hex Buffers And Line Drivers With 3-State Outputs, D0016A, LARGE T&R; Manufacturer: Texas Instruments; tpd @ Nom Voltage(Max)(ns): 20; VCC(Min)(V): 2; ICC @ Nom Voltage(Max)(mA): 0.08; F @ Nom Voltage(Max)(Mhz): 28; Rating: Catalog; Bits(#): 6; Input Type: CMOS
U12 = CMP-0126583-1: Real-Time Microcontroller, LQFP64; Manufacturer: Texas Instruments; SizeZ_mm: 1.6mm; AEC Qualified: No; Core Architecture: C28x; Data Bus Width: 32bits; Frequency_Fixed: 160MHz; Interface: I2C,SPI,UART,CAN,LIN,SCI; Max Supply Voltage: 3.63V; Memory Size: 512KBytes; Memory Type: FLASH; Min Supply Voltage: 1.19V; Number Of A/D Converters: 5; Number Of Adc Channels: 28; Number Of Cores: 1; Number Of I/Os: 17; Number Of I2C Channels: 2; Number Of Pwm Channels: 24; Number Of Timers/Counters: 3; Ram Size: 101KBytes; Standoff Height: 0.05mm; TaMax_C: +125°C; TaMin_C: -40°C; TJmax_C: +150°C
U13 = CMP-0047343-1: Quadruple Bus Buffer Gates With 3-State Outputs, D0014A, LARGE T&R; Manufacturer: Texas Instruments; ICC @ Nom Voltage(Max)(mA): 0.02; Voltage(Nom)(V): 2.5,3.3,5; Bits(#): 4; VCC(Max)(V): 5.5; F @ Nom Voltage(Max)(Mhz): 110; Rating: Catalog; VCC(Min)(V): 2; tpd @ Nom Voltage(Max)(ns): 15.5,9.5,6.5; Output Type: LVTTL

## Sheet TIDA-011008_WiFi Module.SchDoc
size 431 x 279 mm; Date: Not shown in title block; ApprovedBy: Not shown in title block; CheckedBy: Not shown in title block; Author: Not shown in title block; CompanyName: Not shown in title block; Engineer: Not shown in title block; Organization: Not shown in title block; Address1: Not shown in title block; Address2: Not shown in title block; Address3: Not shown in title block; Address4: Not shown in title block; DocumentNumber: 1; Revision: Use project parameter SCH_Rev; SheetNumber: 10; SheetTotal: 10; PageSetup: Record=PageOptions¦CenterHorizontal=True¦CenterVertical=True¦PrintScale=1.00¦XCorrection=1.00¦YCorrection=1.00¦PrintKind=0¦BorderSize=5000000¦LeftOffset=0¦BottomOffset=0¦Orientation=2¦PaperLength=1000¦PaperWidth=1000¦Scale=100¦PaperSource=15¦PrintQuality=600¦MediaType=1¦DitherType=10¦PaperKind=Letter¦PrintScaleMode=1
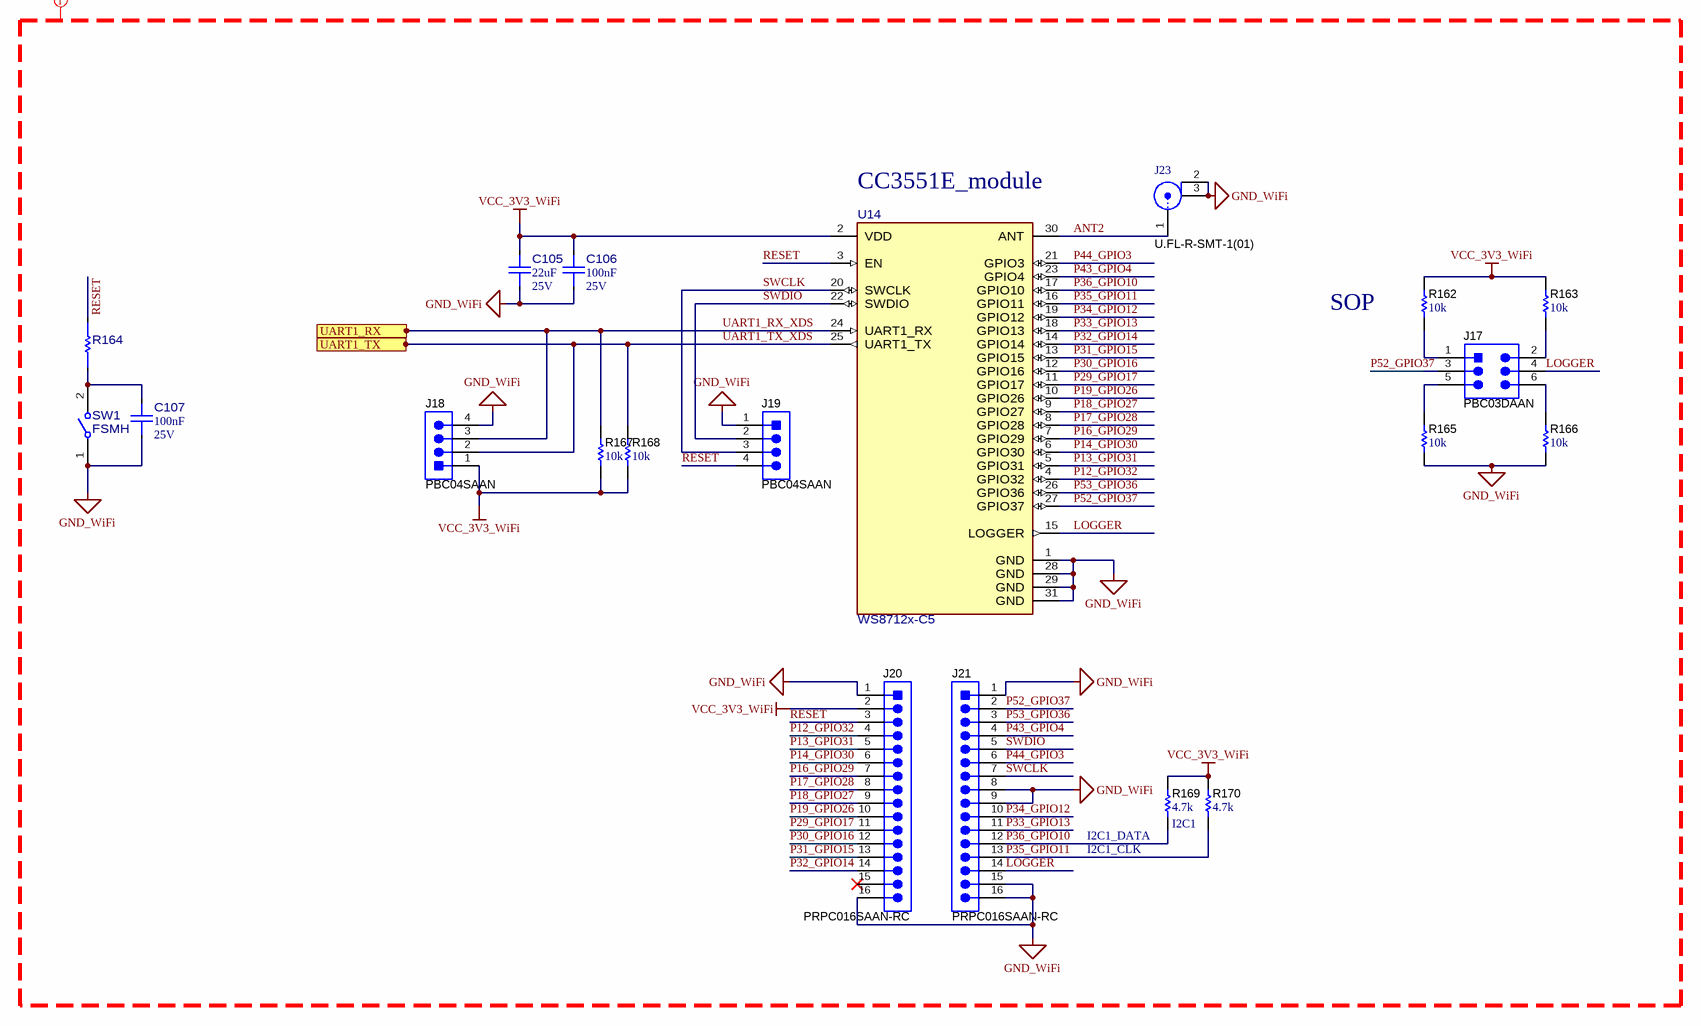
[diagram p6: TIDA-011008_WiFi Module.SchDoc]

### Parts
C105  ValueDisplayed: 22uF  VDC_V: 25V  [FP-GRM188C61E226ME01J_0603-MFG]  (hidden comment: GRM188C61E226ME01J)
C106  ValueDisplayed: 100nF  VDC_V: 25V  [FP-C1608X8R1E104K080AA_0603-MFG]  (hidden comment: C1608X8R1E104K080AA)
C107  ValueDisplayed: 100nF  VDC_V: 25V  [FP-C1608X8R1E104K080AA_0603-MFG]  (hidden comment: C1608X8R1E104K080AA)
J17  PBC03DAAN  [Sullins_PBC03DAAN]
J18  PBC04SAAN  [Sullins_xxC04SAAN]
J19  PBC04SAAN  [Sullins_xxC04SAAN]
J20  PRPC016SAAN-RC  [Sullins_xxxC016SAAN]
J21  PRPC016SAAN-RC  [Sullins_xxxC016SAAN]
J23  U.FL-R-SMT-1(01)  [CONN_UFL-R-SMT-1]
R162  ValueDisplayed: 10k  [0603]  (hidden comment: CRCW060310K0JNEA)
R163  ValueDisplayed: 10k  [0603]  (hidden comment: CRCW060310K0JNEA)
R164  RC0603FR-100RL  [FP-RC0603FR-100RL_0603-MFG]  (value not drawn)
R165  ValueDisplayed: 10k  [0603]  (hidden comment: CRCW060310K0JNEA)
R166  ValueDisplayed: 10k  [0603]  (hidden comment: CRCW060310K0JNEA)
R167  ValueDisplayed: 10k  [0603]  (hidden comment: CRCW060310K0JNEA)
R168  ValueDisplayed: 10k  [0603]  (hidden comment: CRCW060310K0JNEA)
R169  ValueDisplayed: 4.7k  [0603]  (hidden comment: CR0603-JW-472GLF)
R170  ValueDisplayed: 4.7k  [0603]  (hidden comment: CR0603-JW-472GLF)
SW1  FSMH  [FP-FSMH_PTH_SW_6MM0_3MM5-MFG]
U14  WS8712x-C5  [FP-WS8712x-C5_SMD31-MFG]

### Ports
UART1_RX (in), UART1_TX (out)

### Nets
GND_WiFi: C105.1 C106.1 C107.1 J18.4 J19.1 J20.1 J20.16 J21.1 J21.8 J21.9 J21.15 J21.16 J23.2 J23.3 R165.1 R166.1 SW1.1 U14.1(GND) U14.28(GND) U14.29(GND) U14.31(GND)
VCC_3V3_WiFi: C105.2 C106.2 J18.1 J20.2 R162.2 R163.2 R167.2 R168.2 R169.2 R170.2 U14.2(VDD)
ANT2: J23.1 U14.30(ANT)
LOGGER: J17.4 J21.14 U14.15(LOGGER)
P12_GPIO32: J20.4 U14.4(GPIO32)
P13_GPIO31: J20.5 U14.5(GPIO31)
P14_GPIO30: J20.6 U14.6(GPIO30)
P16_GPIO29: J20.7 U14.7(GPIO29)
P17_GPIO28: J20.8 U14.8(GPIO28)
P18_GPIO27: J20.9 U14.9(GPIO27)
P19_GPIO26: J20.10 U14.10(GPIO26)
P29_GPIO17: J20.11 U14.11(GPIO17)
P30_GPIO16: J20.12 U14.12(GPIO16)
P31_GPIO15: J20.13 U14.13(GPIO15)
P32_GPIO14: J20.14 U14.14(GPIO14)
P33_GPIO13: J21.11 U14.18(GPIO13)
P34_GPIO12: J21.10 U14.19(GPIO12)
P35_GPIO11: J21.13 R170.1 U14.16(GPIO11)
P36_GPIO10: J21.12 R169.1 U14.17(GPIO10)
P43_GPIO4: J21.4 U14.23(GPIO4)
P44_GPIO3: J21.6 U14.21(GPIO3)
P52_GPIO37: J17.3 J21.2 U14.27(GPIO37)
P53_GPIO36: J21.3 U14.26(GPIO36)
RESET: J19.4 J20.3 R164.2 U14.3(EN)
SWCLK: J19.3 J21.7 U14.20(SWCLK)
SWDIO: J19.2 J21.5 U14.22(SWDIO)
UART1_RX_XDS: J18.3 R167.1 U14.24(UART1_RX) ; port UART1_RX  [project net UART1_RX]
UART1_TX_XDS: J18.2 R168.1 U14.25(UART1_TX) ; port UART1_TX  [project net UART1_TX]
NetC107_2: C107.2 R164.1 SW1.2
NetJ17_1: J17.1 R162.1
NetJ17_2: J17.2 R163.1
NetJ17_5: J17.5 R165.2
NetJ17_6: J17.6 R166.2

Not connected (* = marked no-connect by the designer): J20 15*

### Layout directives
net class GND_WiFi: ANT2, GND_WiFi, LOGGER, P12_GPIO32, P13_GPIO31, P14_GPIO30, P16_GPIO29, P17_GPIO28, P18_GPIO27, P19_GPIO26, P29_GPIO17, P30_GPIO16, P31_GPIO15, P32_GPIO14, P33_GPIO13, P34_GPIO12, P35_GPIO11, P36_GPIO10, P43_GPIO4, P44_GPIO3, P52_GPIO37, P53_GPIO36, RESET, SWCLK, SWDIO, UART1_RX_XDS, UART1_TX_XDS, VCC_3V3_WiFi

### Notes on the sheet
- (near U14) CC3551E_module
- SOP
- (near R169) I2C1_DATA
- (near R169) I2C1_CLK
- (near R169) I2C1

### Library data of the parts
C105 = CMP-0123328-1: 22 µF ±20% 25V Ceramic Capacitor X5S 0603 (1608 Metric); Manufacturer: Murata; AEC Qualified: No; Cap_F: 22µF; SizeZ_mm: 1mm; TempCo: 22%; Value: 22µF
C106 C107 = CMP-0089959-1: as C65 on sheet TIDA-011008_Control Stage
J17 = CMP-0054565-2: Header, 100mil, 3x2, Gold, TH; Manufacturer: Sullins Connector Solutions; Current_A: 3A; Green_Lifecycle: Active; Shrouded: N; Gender: Male; Green_REACh: Passed; Voltage_V: 1.8kV; Row_Count: 2; RowSpacing_mm: 2.54; Cert_UL: Y
J18 J19 = CMP-0054583-1: as J13 on sheet TIDA-011008_Control Stage
J20 J21 = CMP-0054601-1: Header, 2.54mm, 16x1, Gold, TH; Manufacturer: Sullins Connector Solutions; CNHeader: TRUE; Current_A: 3A; Shrouded: N; Gender: Male; Voltage_V: 36V; Row_Count: 1; Pitch_mm: 2.54; CT: FALSE; Cert_UL: Y
J23 = CMP-0075320-1: Receptacle, Ultra Miniature Coaxial, Male Pin, 50 ohm, SMT; Manufacturer: Hirose Electric Co. Ltd.; CNHeader: False; Gender: Female; ContactFinish: Gold
R162 R163 R165-R168 = CMP-0025701-4: RES, 10 k, 5%, 0.1 W, AEC-Q200 Grade 0, 0603; Manufacturer: Vishay-Dale; Power_W: 100mW; TempCo: 200 ppm/C; Value_Code: 10k0; Value: 10k; EIA_Code: E24; SizeX_mm: 1.6; SizeY_mm: 0.8; SizeZ_mm: 1; Value2: 0.1W; SizeArea_mm2: 1.28; AEC Qualified: Y; VDC_V: 75V; AEC Category: Q200; AEC Grade: 0
R164 = CMP-0123755-1: 0 Ohms Jumper Chip Resistor 0603 (1608 Metric) Moisture Resistant Thick Film; Manufacturer: Yageo; AEC Qualified: No; Res_ohm: 0; SizeZ_mm: 0.55mm; Tolerance_%: 1%; Value: 0
R169 R170 = CMP-0025696-3: as R107 on sheet TIDA-011008_Control Stage
SW1 = CMP-0126760-1: Switch Tactile SPST Rectangular Button PC Pins 0.05A 24VDC 20000Cycle 1.3N Thru-Hole Bulk; Manufacturer: TE Connectivity; Circuit: SPST-NO; SizeZ_mm: 5.62mm; VDC_V: 24V; AEC Qualified: No; Coil Resistance_ohm: 50mΩ; Contact Current Rating: 50mA; Electromechanical Life: 100000Cycles; Operating Force: 130gf
U14 = CMP-0127891-1: Wi-Fi 6 & Bluetooth Module; Manufacturer: Silent Smart; SizeZ_mm: 2.8mm

## Sheet TIDA-011008_ACDC_Leg.SchDoc
size 431 x 279 mm; Date: Not shown in title block; ApprovedBy: Not shown in title block; CheckedBy: Not shown in title block; Author: Not shown in title block; CompanyName: Not shown in title block; Engineer: Not shown in title block; Organization: Not shown in title block; Address1: Not shown in title block; Address2: Not shown in title block; Address3: Not shown in title block; Address4: Not shown in title block; DocumentNumber: 1; Revision: Use project parameter SCH_Rev; SheetNumber: 5; SheetTotal: 10; PageSetup: Record=PageOptions¦CenterHorizontal=True¦CenterVertical=True¦PrintScale=1.00¦XCorrection=1.00¦YCorrection=1.00¦PrintKind=0¦BorderSize=5000000¦LeftOffset=0¦BottomOffset=0¦Orientation=2¦PaperLength=1000¦PaperWidth=1000¦Scale=100¦PaperSource=15¦PrintQuality=600¦MediaType=1¦DitherType=10¦PaperKind=Letter¦PrintScaleMode=1
Used 2 times, as channels U_TIDA-011008_ACDC_Leg1, U_TIDA-011008_ACDC_Leg2. Parts and nets are listed once, with the designators drawn on the sheet.
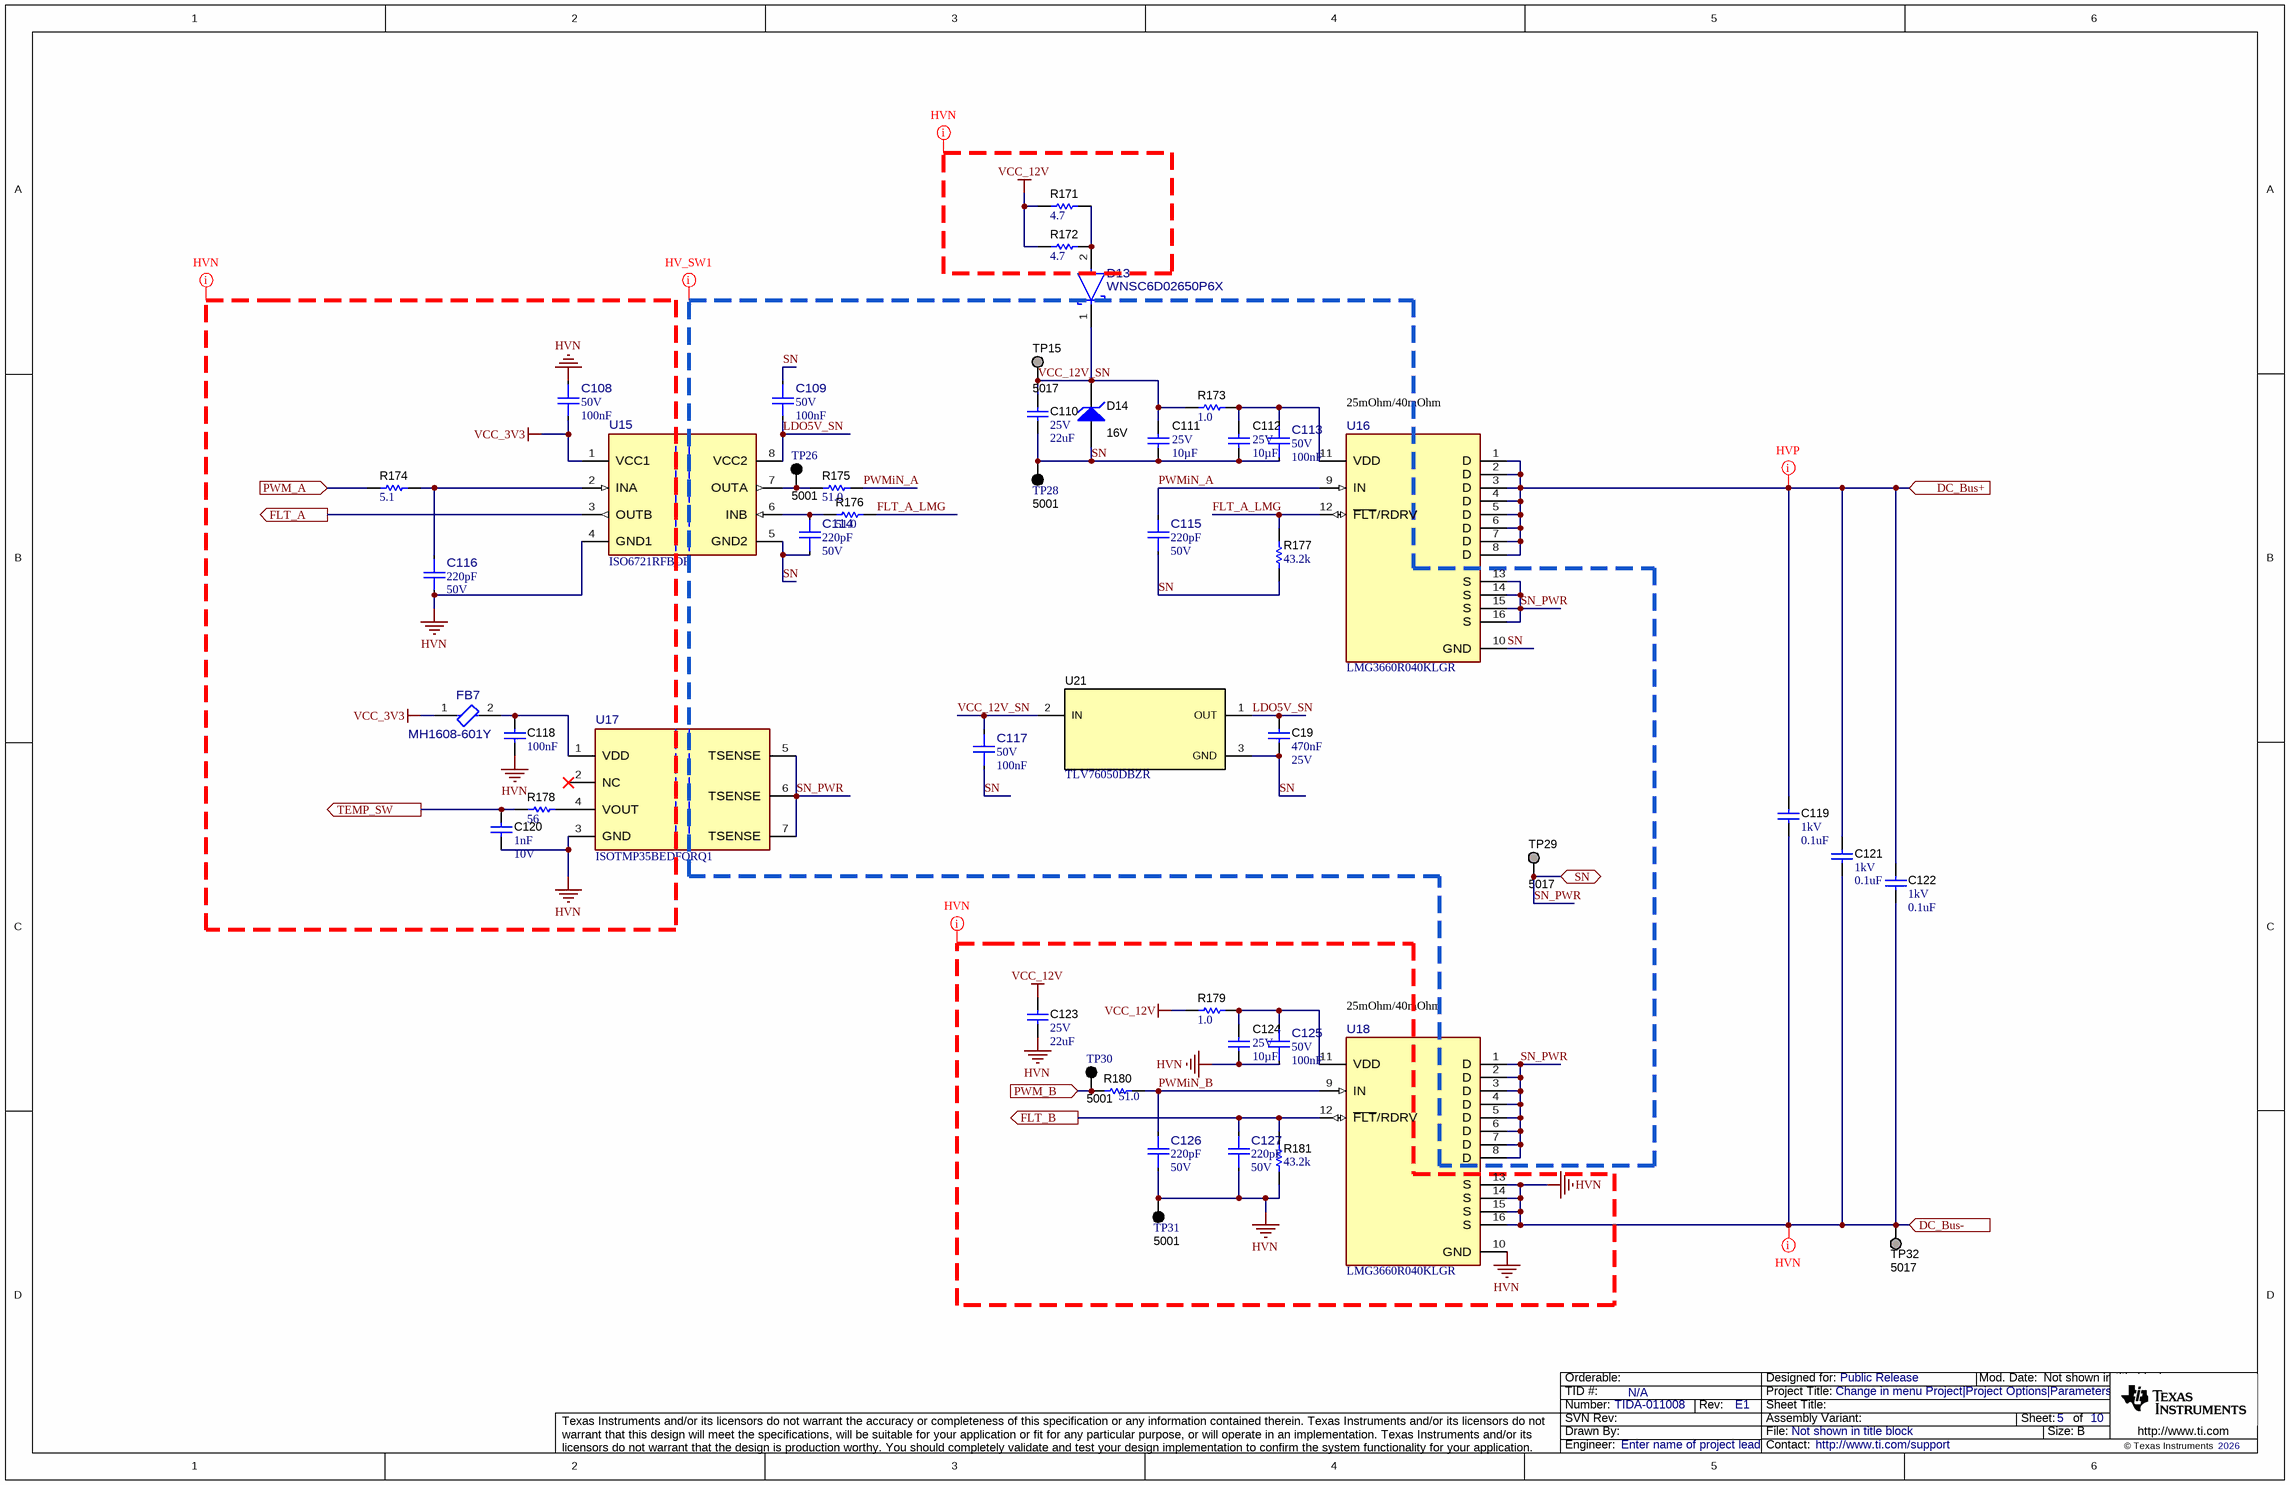
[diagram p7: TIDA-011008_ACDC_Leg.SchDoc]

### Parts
C19  Cap_F: 470nF  VDC_V: 25V  [0603]  (hidden comment: GRM188R71E474KA12D)
C108  VDC_V: 50V  Cap_F: 100nF  [FP-GCM188R71H104KA57J_0603-MFG]  (hidden comment: GCM188R71H104KA57J)
C109  VDC_V: 50V  Cap_F: 100nF  [FP-GCM188R71H104KA57J_0603-MFG]  (hidden comment: GCM188R71H104KA57J)
C110  VDC_V: 25V  ValueDisplayed: 22uF  [1210_280]  (hidden comment: 12103D226MAT2A)
C111  VDC_V: 25V  ValueDisplayed: 10µF  [1206_180]  (hidden comment: TMK316AB7106KLHT)
C112  VDC_V: 25V  ValueDisplayed: 10µF  [1206_180]  (hidden comment: TMK316AB7106KLHT)
C113  VDC_V: 50V  Cap_F: 100nF  [FP-GCM188R71H104KA57J_0603-MFG]  (hidden comment: GCM188R71H104KA57J)
C114  ValueDisplayed: 220pF  VDC_V: 50V  [FP-C0603C221J5GAC7867_0603-MFG]  (hidden comment: C0603C221J5GAC7867)
C115  ValueDisplayed: 220pF  VDC_V: 50V  [FP-C0603C221J5GAC7867_0603-MFG]  (hidden comment: C0603C221J5GAC7867)
C116  ValueDisplayed: 220pF  VDC_V: 50V  [FP-C0603C221J5GAC7867_0603-MFG]  (hidden comment: C0603C221J5GAC7867)
C117  VDC_V: 50V  Cap_F: 100nF  [FP-GCM188R71H104KA57J_0603-MFG]  (hidden comment: GCM188R71H104KA57J)
C118  Cap_F: 100nF  [0603]  (hidden comment: 06033C104JAT2A)
C119  VDC_V: 1kV  ValueDisplayed: 0.1uF  [1812_254]  (hidden comment: C1812V104KDRACTU)
C120  Cap_F: 1nF  VDC_V: 10V  [0603]  (hidden comment: 0603ZC102KAT2A)
C121  VDC_V: 1kV  ValueDisplayed: 0.1uF  [1812_254]  (hidden comment: C1812V104KDRACTU)
C122  VDC_V: 1kV  ValueDisplayed: 0.1uF  [1812_254]  (hidden comment: C1812V104KDRACTU)
C123  VDC_V: 25V  ValueDisplayed: 22uF  [1210_280]  (hidden comment: 12103D226MAT2A)
C124  VDC_V: 25V  ValueDisplayed: 10µF  [1206_180]  (hidden comment: TMK316AB7106KLHT)
C125  VDC_V: 50V  Cap_F: 100nF  [FP-GCM188R71H104KA57J_0603-MFG]  (hidden comment: GCM188R71H104KA57J)
C126  ValueDisplayed: 220pF  VDC_V: 50V  [FP-C0603C221J5GAC7867_0603-MFG]  (hidden comment: C0603C221J5GAC7867)
C127  ValueDisplayed: 220pF  VDC_V: 50V  [FP-C0603C221J5GAC7867_0603-MFG]  (hidden comment: C0603C221J5GAC7867)
D13  WNSC6D02650P6X  [FP-WNSC6D02650P6X_SOD123-IPC_C]
D14  value 16V  [SOD-123]  (hidden comment: BZT52C16-7-F)
FB7  MH1608-601Y  [FP-MH1608-601Y_0603-MFG]
R171  ValueDisplayed: 4.7  [1206]  (hidden comment: CRCW12064R70JNEAHP)
R172  ValueDisplayed: 4.7  [1206]  (hidden comment: CRCW12064R70JNEAHP)
R173  ValueDisplayed: 1.0  [0603]  (hidden comment: CRCW06031R00JNEA)
R174  ValueDisplayed: 5.1  [0603]  (hidden comment: CRCW06035R10JNEA)
R175  ValueDisplayed: 51.0  [0603]  (hidden comment: RC0603FR-0751RL)
R176  ValueDisplayed: 51.0  [0603]  (hidden comment: RC0603FR-0751RL)
R177  ValueDisplayed: 43.2k  [0603]  (hidden comment: RC0603FR-0743K2L)
R178  ValueDisplayed: 56  [0603]  (hidden comment: CRCW060356R0JNEA)
R179  ValueDisplayed: 1.0  [0603]  (hidden comment: CRCW06031R00JNEA)
R180  ValueDisplayed: 51.0  [0603]  (hidden comment: RC0603FR-0751RL)
R181  ValueDisplayed: 43.2k  [0603]  (hidden comment: RC0603FR-0743K2L)
TP15  5017  [Keystone_5017]
TP26  5001  [Keystone5001]
TP28  5001  [Keystone5001]
TP29  5017  [Keystone_5017]
TP30  5001  [Keystone5001]
TP31  5001  [Keystone5001]
TP32  5017  [Keystone_5017]
U15  ISO6721RFBDR  [D0008A-MFG]
U16  LMG3660R040KLGR  [KLG0016A-MFG]
U17  ISOTMP35BEDFQRQ1  [DFQ0007A-MFG]
U18  LMG3660R040KLGR  [KLG0016A-MFG]
U21  TLV76050DBZR  [DBZ0003A_N]

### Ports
DC_Bus+ (in), DC_Bus- (in), FLT_A (out), FLT_B (out), PWM_A (in), PWM_B (in), SN (bidir), TEMP_SW (out)

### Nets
HVN: C108.1 C116.2 C118.2 C119.2 C120.2 C121.2 C122.2 C123.2 C124.2 C125.1 C126.1 C127.1 R181.1 TP31.1 TP32.1 U15.4(GND1) U17.3(GND) U18.10(GND) U18.13(S) U18.14(S) U18.15(S) U18.16(S) ; port DC_Bus-
VCC_3V3: C108.2 FB7.1 U15.1(VCC1)
VCC_12V: C123.1 R171.1 R172.1 R179.1
DC_Bus+: C119.1 C121.1 C122.1 U16.1(D) U16.2(D) U16.3(D) U16.4(D) U16.5(D) U16.6(D) U16.7(D) U16.8(D) ; port DC_Bus+
FLT_A: U15.3(OUTB) ; port FLT_A
FLT_A_LMG: R176.2 R177.2 U16.12(~{FLT}/RDRV)
FLT_B: C127.2 R181.2 U18.12(~{FLT}/RDRV) ; port FLT_B
LDO5V_SN: C19.1 C109.2 U15.8(VCC2) U21.1(OUT)
PWM_A: R174.1 ; port PWM_A
PWM_B: R180.1 TP30.1 ; port PWM_B
PWMiN_A: C115.2 R175.2 U16.9(IN)
PWMiN_B: C126.2 R180.2 U18.9(IN)
SN: C19.2 C109.1 C110.2 C111.2 C112.2 C113.1 C114.1 C115.1 C117.1 D14.2(A) R177.1 TP28.1 U15.5(GND2) U16.10(GND) U21.3(GND)
SN_PWR: TP29.1 U16.13(S) U16.14(S) U16.15(S) U16.16(S) U17.5(TSENSE) U17.6(TSENSE) U17.7(TSENSE) U18.1(D) U18.2(D) U18.3(D) U18.4(D) U18.5(D) U18.6(D) U18.7(D) U18.8(D) ; port SN
TEMP_SW: C120.1 R178.1 ; port TEMP_SW
VCC_12V_SN: C110.1 C111.1 C117.2 D13.1(K) D14.1(K) R173.1 TP15.1 U21.2(IN)
NetC112_1: C112.1 C113.2 R173.2 U16.11(VDD)
NetC114_2: C114.2 R176.1 U15.6(INB)
NetC116_1: C116.1 R174.2 U15.2(INA)
NetC118_1: C118.1 FB7.2 U17.1(VDD)
NetC124_1: C124.1 C125.2 R179.2 U18.11(VDD)
NetD13_2: D13.2(A) R171.2 R172.2
NetR175_1: R175.1 TP26.1 U15.7(OUTA)
NetR178_2: R178.2 U17.4(VOUT)

Not connected (* = marked no-connect by the designer): U17 2(NC)*

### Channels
U_TIDA-011008_ACDC_Leg1: designators end in _U_TIDA-011008_ACDC_Leg1; ports DC_Bus+=DC_Bus+ DC_Bus-=DC_Bus- FLT_A=FLT_1A FLT_B=FLT_1B PWM_A=PWM_1A PWM_B=PWM_1B SN=SN1 TEMP_SW=TEMP_SW1
U_TIDA-011008_ACDC_Leg2: designators end in _U_TIDA-011008_ACDC_Leg2; ports DC_Bus+=DC_Bus+ DC_Bus-=DC_Bus- FLT_A=FLT_2A FLT_B=FLT_2B PWM_A=PWM_2A PWM_B=PWM_2B SN=SN2 TEMP_SW=TEMP_SW2

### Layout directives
net class HVN: DC_Bus-, FLT_A_LMG, HVN, LDO5V_SN, PWMiN_A, PWMiN_B, SN, SN_PWR, VCC_3V3, VCC_12V, VCC_12V_SN
net class HV_SW1: FLT_A_LMG, HVN, LDO5V_SN, PWMiN_A, PWMiN_B, SN, SN_PWR, VCC_12V, VCC_12V_SN
net class HVP: DC_Bus+

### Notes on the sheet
- 25mOhm/40mOhm

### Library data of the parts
C19 = CMP-0007424-4: CAP, CERM, 0.47 uF, 25 V, +/- 10%, X7R, 0603; Manufacturer: MuRata; TaMin_C: -55°C; Polarized: N; SizeAreaWB_mm2: 4.68; Value1: Unknown; U/M: EA; Value: 0.47uF; TaMax_C: 125°C; SizeZ_mm: 1; SizeX_mm: 1.6; SizeY_mm: 0.8; SizeArea_mm2: 1.28; AEC Category: Q200
C108 C109 C113 C117 C125 = CMP-0095617-1: as C84 on sheet TIDA-011008_Control Stage
C110 C123 = CMP-0009063-2: CAP, CERM, 22 uF, 25 V, +/- 20%, X5R, 1210; Manufacturer: AVX; TaMin_C: -55°C; Polarized: N; SizeAreaWB_mm2: 14.7; Value1: Unknown; U/M: EA; Value: 22uF; TaMax_C: 85°C; SizeZ_mm: 2.8; SizeX_mm: 3.2; SizeY_mm: 2.5; Cap_Case: 1210; SizeArea_mm2: 8; Cap_F: 22µF; AEC Category: Q200
C111 C112 C124 = CMP-0750154-1: CAP, CERM, 10 µF, 25 V,+/- 10%, X7R, AEC-Q200 Grade 1, 1206; Manufacturer: Taiyo Yuden; AEC Qualified: Y; SizeZ_mm: 1.8; TaMax_C: 125°C; TaMin_C: -55°C; Cap_Case: 1206; Polarized: N; AEC Grade: 1; SizeY_mm: 1.6; Value: 10uF; SizeX_mm: 3.2; SizeAreaWB_mm2: 10.92; AEC Category: Q200; U/M: EA; SizeArea_mm2: 5.12
C114-C116 C126 C127 = CMP-0045670-1: 220 pF ±5% 50V Ceramic Capacitor C0G, NP0 0603 (1608 Metric); Manufacturer: KEMET; AEC Qualified: No; SizeZ_mm: 0.87mm; TempCo: 30ppm/°C; Value: 220pF
C118 = CMP-0006752-5: CAP, CERM, 0.1 uF, 25 V, +/- 5%, X7R, 0603; Manufacturer: AVX; TaMin_C: -55°C; ESR_ohm: 0.05; Polarized: N; SizeAreaWB_mm2: 4.68; Value1: 0.05 ohm; U/M: EA; Value: 0.1uF; TaMax_C: 125°C; SizeZ_mm: 1; SizeX_mm: 1.6; SizeY_mm: 0.8; Value2: 25V; SizeArea_mm2: 1.28; AEC Category: Q200
C119 C121 C122 = CMP-0009324-2: CAP, CERM, 0.1 uF, 1000 V, +/- 10%, X7R, 1812; Manufacturer: Kemet; TaMin_C: -55°C; Polarized: N; SizeAreaWB_mm2: 23.1; Value1: Unknown; U/M: EA; Value: 0.1uF; TaMax_C: 125°C; SizeZ_mm: 2.54; SizeX_mm: 4.5; SizeY_mm: 3.2; Cap_Case: 1812; Value2: 1000V; SizeArea_mm2: 14.4; Cap_F: 100nF; AEC Category: Q200
C120 = CMP-0006813-4: CAP, CERM, 1000 pF, 10 V, +/- 10%, X7R, 0603; Manufacturer: AVX; TaMin_C: -55°C; Polarized: N; SizeAreaWB_mm2: 4.68; Value1: Unknown; U/M: EA; Value: 1000pF; TaMax_C: 125°C; SizeZ_mm: 1; SizeX_mm: 1.6; SizeY_mm: 0.8; SizeArea_mm2: 1.28; AEC Category: Q200
D13 = CMP-0128427-1: Rectifier Diode, Schottky, 1 Phase, 1 Element, 2A, 700V V(RRM), Silicon Carbide; Manufacturer: WeEn Semiconductors; AEC Qualified: No; SizeZ_mm: 1.25mm; TJmax_C: 175°C; Cap_F: 103pF; Max Surge Forward Current: 14A; Peak Reverse Current: 0.2uA; Standoff Height: 0mm
D14 = CMP-0005769-4: Diode, Zener, 16 V, 500 mW, AEC-Q101, SOD-123; Manufacturer: Diodes Inc.; SizeZ_mm: 1.35; AEC Qualified: Y; SizeX_mm: 3.85; AEC Category: Q101; Power_W: 500mW; SizeY_mm: 1.7; Value1: 0.5W; SizeAreaWB_mm2: 13.095; SizeArea_mm2: 6.545; RJA_CperW: 338
FB7 = CMP-0037505-1: 600 Ohms @ 100 MHz 1 Power, Signal Line Ferrite Bead 0603 (1608 Metric) 1A 200mOhm; Manufacturer: Bourns; DCR_ohm: 0.2; SizeZ_mm: 1mm; AEC Qualified: No; Impedance At Frequency: 600Ω @ 100MHz; Test Frequency: 100MHz; Tolerance_%: 25%
R171 R172 = CMP-0018694-3: RES, 4.7, 5%, 0.75 W, AEC-Q200 Grade 0, 1206; Manufacturer: Vishay-Dale; Power_W: 750mW; TempCo: 200 ppm/C; Value_Code: 4R70; Value: 4.7; EIA_Code: E24; SizeX_mm: 3.2; SizeY_mm: 1.6; SizeZ_mm: 1.35; Value2: 0.75W; SizeArea_mm2: 5.12; AEC Qualified: Y; AEC Grade: 0; AEC Category: Q200
R173 R179 = CMP-0025743-4: RES, 1.0, 5%, 0.1 W, AEC-Q200 Grade 0, 0603; Manufacturer: Vishay-Dale; Power_W: 100mW; TempCo: 200 ppm/C; Value_Code: 1R00; Value: 1.0; EIA_Code: E24; Res_ohm: 1; SizeX_mm: 1.6; SizeY_mm: 0.8; Value2: 0.1W; SizeArea_mm2: 1.28; AEC Qualified: Y; VDC_V: 75V; AEC Category: Q200; AEC Grade: 0
R174 = CMP-0025834-4: RES, 5.1, 5%, 0.1 W, AEC-Q200 Grade 0, 0603; Manufacturer: Vishay-Dale; Power_W: 100mW; TempCo: 200 ppm/C; Value_Code: 5R10; Value: 5.1; EIA_Code: E24; SizeX_mm: 1.6; SizeY_mm: 0.8; SizeZ_mm: 1; Value2: 0.1W; SizeArea_mm2: 1.28; AEC Qualified: Y; VDC_V: 75V; AEC Category: Q200; AEC Grade: 0
R175 R176 R180 = CMP-0023169-5: RES, 51.0, 1%, 0.1 W, 0603; Manufacturer: Yageo; Power_W: 100mW; TempCo: 100 ppm/C; Value_Code: 51R0; Value: 51.0; Res_ohm: 51; SizeX_mm: 1.6; SizeY_mm: 0.8; SizeZ_mm: 1; Value2: 0.1W; SizeArea_mm2: 1.28; AEC Qualified: N; VDC_V: 75V; AEC Category: Q200; SizeAreaWB_mm2: 4.68
R177 R181 = CMP-0023112-5: RES, 43.2 k, 1%, 0.1 W, 0603; Manufacturer: Yageo; Power_W: 100mW; TempCo: 100 ppm/C; Value_Code: 43k2; Value: 43.2k; EIA_Code: E96; SizeX_mm: 1.6; SizeY_mm: 0.8; SizeZ_mm: 1; Value2: 0.1W; SizeArea_mm2: 1.28; AEC Qualified: N; VDC_V: 75V; AEC Category: Q200; SizeAreaWB_mm2: 4.68
R178 = CMP-0025829-4: RES, 56, 5%, 0.1 W, AEC-Q200 Grade 0, 0603; Manufacturer: Vishay-Dale; Power_W: 100mW; TempCo: 200 ppm/C; Value_Code: 56R0; Value: 56; EIA_Code: E24; SizeX_mm: 1.6; SizeY_mm: 0.8; SizeZ_mm: 1; Value2: 0.1W; SizeArea_mm2: 1.28; AEC Qualified: Y; VDC_V: 75V; AEC Category: Q200; AEC Grade: 0
TP15 TP29 TP32 = CMP-0078225-3: PC Test Point, SMT; Manufacturer: Keystone Electronics
TP26 TP28 TP30 TP31 = CMP-0055138-2: as TP24 on sheet TIDA-011008_Control Stage
U15 = CMP-0127257-1: General-purpose, dual-channel, 1/1 reverse pinout digital isolator 8-SOIC -40 to 125; Manufacturer: Texas Instruments; Part Number: ISO6721RBDR; SizeZ_mm: 1.75mm; AEC Qualified: No; Max Supply Voltage: 5.5V; Min Supply Voltage: 1.71V; Standoff Height: 0.11mm; TaMax_C: +125°C; TaMin_C: -40°C; TJmax_C: +150°C
U16 U18 = CMP-0128366-1: Manufacturer: Texas Instruments; SizeZ_mm: 2.35mm; AEC Qualified: Unknown; AEC Grade: NA; Standoff Height: 0mm
U17 = CMP-0122473-1: Automotive ±1.5°C, 3-kVRMS Isolated Temperature Sensor With Analog Output With < 2 Seconds Response Time and 500VRMS Working Voltage; Manufacturer: Texas Instruments; SizeZ_mm: 1.75mm; AEC Qualified: Yes; AEC Grade: Grade 0; Max Supply Voltage: 5.5V; Min Supply Voltage: 2.3V; Operating Supply Current: 10uA; Sensor Output: Analog Voltage; Standoff Height: 0.11mm; TaMax_C: +150°C; TaMin_C: -40°C; TJmax_C: +155°C
U21 = CMP-0074892-1: 100-mA, 30-V, Fixed-Output, Linear-Voltage Regulator, DBZ0003A (SOT-23-3); Alternate PartNumber: TLV76050DBZT; Alternate Manufacturer: Texas Instruments; SizeAreaWB_mm2: 14.0; SizeZ_mm: 1.12; SizeX_mm: 2.5; SizeY_mm: 3.0; SizeArea_mm2: 7.5; CompType: IC; AEC Qualified: N; AEC Category: Q200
